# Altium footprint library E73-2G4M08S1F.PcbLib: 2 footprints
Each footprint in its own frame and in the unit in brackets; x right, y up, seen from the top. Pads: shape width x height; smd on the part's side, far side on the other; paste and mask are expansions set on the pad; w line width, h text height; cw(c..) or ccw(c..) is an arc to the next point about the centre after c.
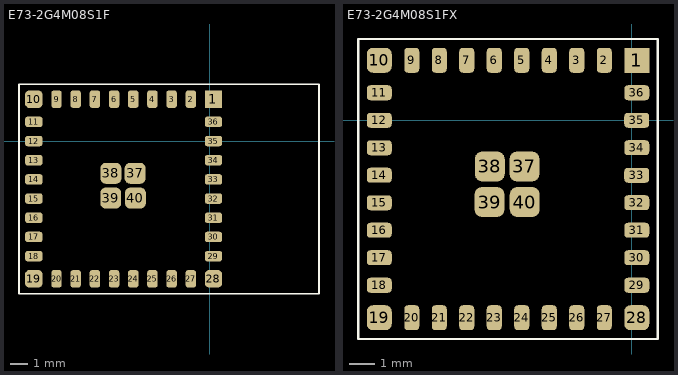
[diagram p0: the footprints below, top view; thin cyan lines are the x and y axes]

## E73-2G4M08S1F [mm]
pads (40):
  rect 1x1 smd paste+0 mask+0: 1(0.2,2.4)
  rrect50% 0.6x1 smd paste+0 mask+0: 2(-1.1,2.4) 3(-2.2,2.4) 4(-3.3,2.4) 5(-4.4,2.4) 6(-5.5,2.4) 7(-6.6,2.4) 8(-7.7,2.4) 9(-8.8,2.4) 20(-8.8,-7.9) 21(-7.7,-7.9) 22(-6.6,-7.9) 23(-5.5,-7.9) 24(-4.4,-7.9) 25(-3.3,-7.9) 26(-2.2,-7.9) 27(-1.1,-7.9)
  rrect50% 1x1 smd paste+0 mask+0: 10(-10.1,2.4) 19(-10.1,-7.9) 28(0.2,-7.9)
  rrect50% 1x0.6 smd paste+0 mask+0: 11(-10.1,1.1) 12(-10.1,0) 13(-10.1,-1.1) 14(-10.1,-2.2) 15(-10.1,-3.3) 16(-10.1,-4.4) 17(-10.1,-5.5) 18(-10.1,-6.6) 29(0.2,-6.6) 30(0.2,-5.5) 31(0.2,-4.4) 32(0.2,-3.3) 33(0.2,-2.2) 34(0.2,-1.1) 35(0.2,0) 36(0.2,1.1)
  rrect50% 1.2x1.2 smd paste+0 mask+0: 37(-4.29,-1.85) 38(-5.68,-1.85) 39(-5.69,-3.27) 40(-4.28,-3.27)
Top Overlay:
  lines w0.1: -10.95,-8.75 6.25,-8.75 6.25,3.25 -10.95,3.25 -10.95,-8.75

## E73-2G4M08S1FX [mm]
pads (40):
  rect 1x1 smd paste+0 mask+0: 1(0.2,2.4)
  rrect50% 0.6x1 smd paste+0 mask+0: 2(-1.1,2.4) 3(-2.2,2.4) 4(-3.3,2.4) 5(-4.4,2.4) 6(-5.5,2.4) 7(-6.6,2.4) 8(-7.7,2.4) 9(-8.8,2.4) 20(-8.8,-7.9) 21(-7.7,-7.9) 22(-6.6,-7.9) 23(-5.5,-7.9) 24(-4.4,-7.9) 25(-3.3,-7.9) 26(-2.2,-7.9) 27(-1.1,-7.9)
  rrect50% 1x1 smd paste+0 mask+0: 10(-10.1,2.4) 19(-10.1,-7.9) 28(0.2,-7.9)
  rrect50% 1x0.6 smd paste+0 mask+0: 11(-10.1,1.1) 12(-10.1,0) 13(-10.1,-1.1) 14(-10.1,-2.2) 15(-10.1,-3.3) 16(-10.1,-4.4) 17(-10.1,-5.5) 18(-10.1,-6.6) 29(0.2,-6.6) 30(0.2,-5.5) 31(0.2,-4.4) 32(0.2,-3.3) 33(0.2,-2.2) 34(0.2,-1.1) 35(0.2,0) 36(0.2,1.1)
  rrect50% 1.2x1.2 smd paste+0 mask+0: 37(-4.29,-1.85) 38(-5.68,-1.85) 39(-5.69,-3.27) 40(-4.28,-3.27)
Top Overlay:
  lines w0.1: 1.016,-8.75 -10.95,-8.75 -10.95,3.25 1.016,3.25 ; 1.05,-8.75 1.05,3.25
